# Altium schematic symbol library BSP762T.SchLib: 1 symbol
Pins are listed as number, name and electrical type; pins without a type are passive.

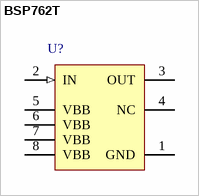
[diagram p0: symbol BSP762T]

## BSP762T
designator U?
Smart Power High-Side-Switch, 1 Channel, 2.4 A Load Current, -40 to 150 degC, PG-DSO-8-24, Reel, Green; Manufacturer: Infineon; PartNumber: BSP762T; Channels: 1; Green: TRUE; Group: Automotive Qualified; Load Current (typ): 2.4 A; Ptot (max): 1.5 W; Recommended Operating Voltage Max.: 34 V; Recommended Operating Voltage Min.: 5 V; RON @ 25degreesC: 100 mOhm; RON(max) @ 150degreesC: 200 mOhm; toff (max): 230 us; ton (max): 170 us
footprint INF-PG-DSO-8-24_N (SOP, 8-Leads, Body 4.9x3.9mm, Pitch 1.27mm, IPC Medium Density)
footprint INF-PG-DSO-8-24_L (SOP, 8-Leads, Body 4.9x3.9mm, Pitch 1.27mm, IPC High Density)
footprint INF-PG-DSO-8-24_M (SOP, 8-Leads, Body 4.9x3.9mm, Pitch 1.27mm, IPC Low Density)
pins: 1 GND (power) "Logic ground", 2 IN (in) "Input, activates the power switch in case of logic high signal.", 3 OUT (power) "Output to the load.", 4 NC "Not connected.", 5 VBB (power) "Positive power supply voltage.", 6 VBB (power) "Positive power supply voltage.", 7 VBB (power) "Positive power supply voltage.", 8 VBB (power) "Positive power supply voltage."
